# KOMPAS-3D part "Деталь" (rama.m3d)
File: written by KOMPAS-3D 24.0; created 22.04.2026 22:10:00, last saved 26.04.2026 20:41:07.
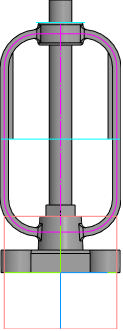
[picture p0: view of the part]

Document properties: Автор: mrdid; Полное имя файла: C:\Работа\VSO2130M-F-S Клапан запорный DN.ru Ду-x Ру40\DN15\rama.m3d

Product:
- Part/product: Деталь
    Масса: 0.336692

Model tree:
1. Эскиз:2
2. Элемент выдавливания:1
     Расстояние 1 = 10
3. Эскиз:3  (with: Грань.Элемент выдавливания:1, Ребро.Элемент выдавливания:1)
4. Элемент выдавливания:2
     Расстояние 2 = 10
5. Массив по сетке:1  (with: Элемент выдавливания:2, Эскиз:3)  (4 pattern instances)
     Угол раствора = 90
6. Эскиз:4  (with: Грань.Элемент выдавливания:1)
7. Элемент выдавливания:3
     Угол 1 = -3
8. Эскиз:5  (with: Грань.Элемент выдавливания:3, Ребро.Элемент выдавливания:3)
9. Элемент выдавливания:4
10. Эскиз:23  (with: Грань.Элемент выдавливания:4, Ребро.Элемент выдавливания:4)
11. Элемент выдавливания:21  (labels: Деталь2; Грань.Твердое тело1)
     Расстояние 1 = 90.9875
12. Эскиз:7  (with: Грань.Элемент выдавливания:4, Ребро.Элемент выдавливания:3)
13. Элемент выдавливания:6  (with: Грань.Элемент выдавливания:3)
     Расстояние 2 = 5
14. Смещенная плоскость:4  (labels: Деталь2; Грань.Твердое тело1)
     Расстояние = 10
15. Эскиз:24  (with: Ребро.Элемент выдавливания:3)
16. Элемент выдавливания:22
     Расстояние 2 = 10
17. Эскиз:25  (with: Ребро.Элемент выдавливания:3)
18. Эскиз:26  (with: Ребро.Элемент выдавливания:3)
19. Элемент по траектории:1
     Длина траектории = 250.223
20. Скругление:8  (with: Ребро.Элемент по траектории:1)
     Радиус = 2
21. Скругление:9  (with: Ребро.Элемент по траектории:1)
     Радиус = 2
22. Смещенная плоскость:5  (with: Грань.Элемент выдавливания:1)
23. Эскиз:27  (with: Вершина.Элемент по траектории:1)
24. Элемент выдавливания:23  (with: Грань.Элемент выдавливания:22)
     Расстояние 2 = -41.7375
25. Скругление:1  (with: Ребро.Элемент выдавливания:1)
     Радиус = 1.5
26. Скругление:10  (with: Ребро.Элемент выдавливания:22)
     Радиус = 1

Expressions: D2/2-3; D2-3*2; DN/2; DN/4; H/4
Referenced files in C:\Работа\VSO2130M-F-S Клапан запорный DN.ru Ду-x Ру40\DN15\: VSO2130M-F-S DN15 PN40  Клапан запорный сильфонный DN.ru.a3d
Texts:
  DN+5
